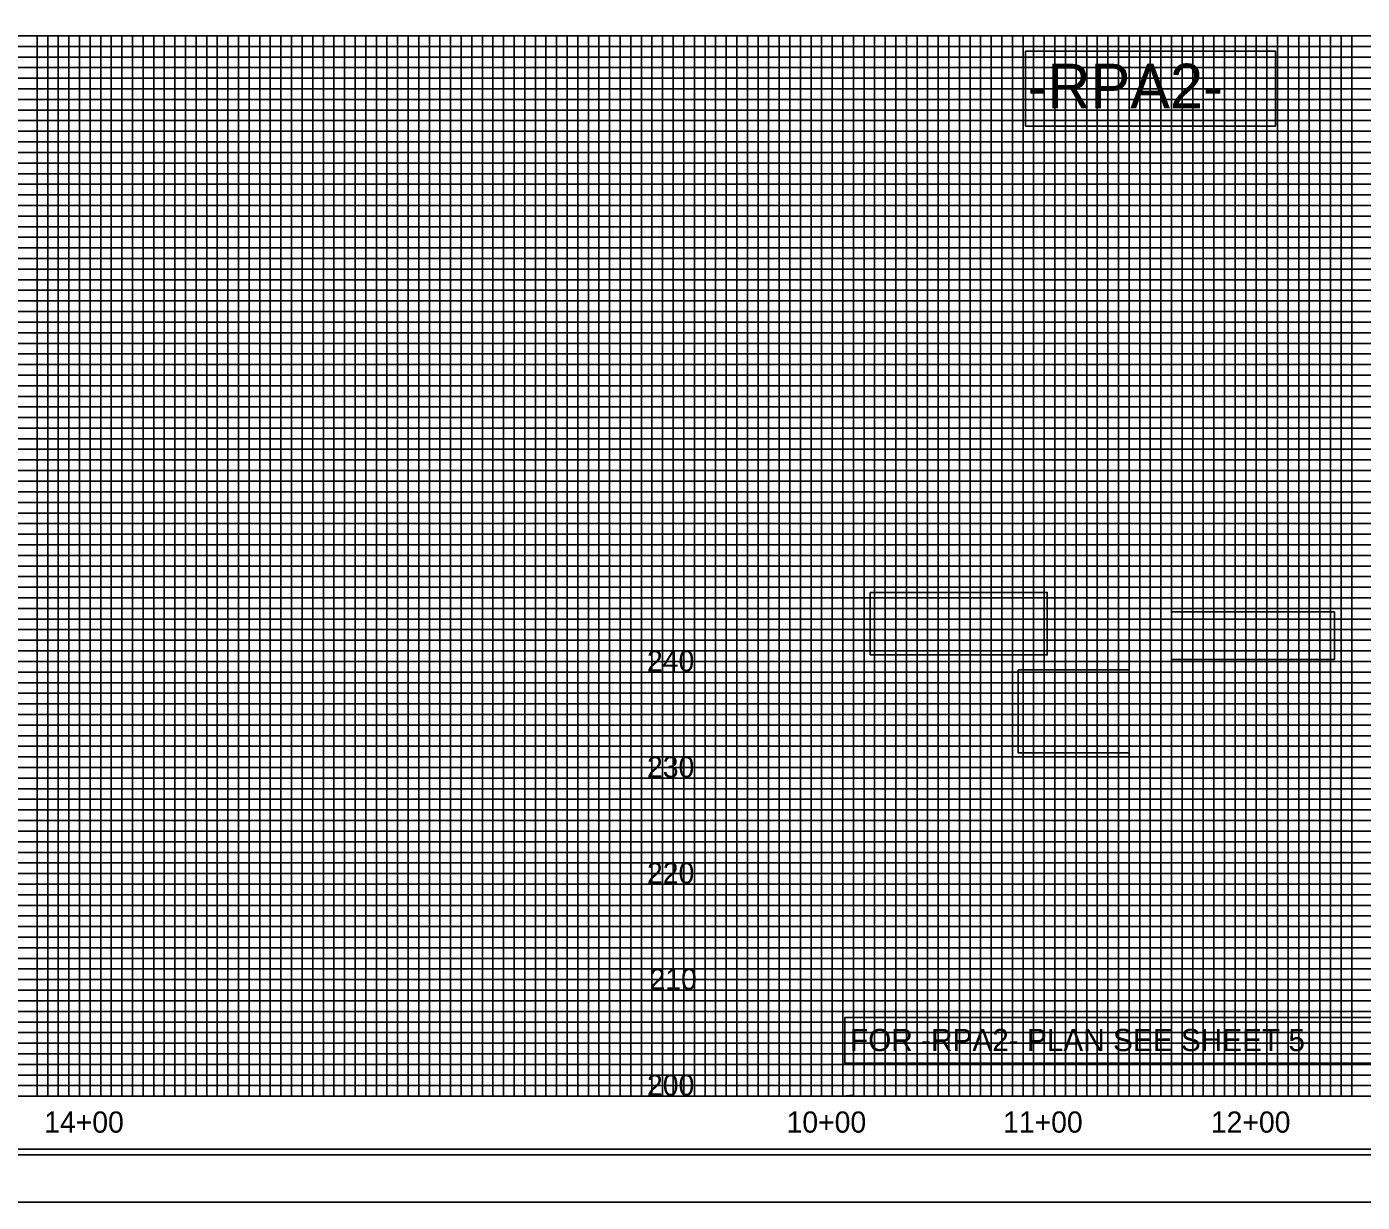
# Model space of a CAD drawing. Extents: x 1810963 to 1812908, y 722070 to 723170.
# Drawn here: x 1811601 to 1812230, y 722070 to 722624 of the extents above; entities that cross this region are included whole.
import ezdxf

# ---------------------------------------------------------------- set-up
doc = ezdxf.new("R2010")
doc.units = 0
for name, color, linetype in [('Exist Horizontal Alignment Tick Label', 7, 'Continuous'), ('Old_Level_11', 7, 'Continuous'), ('Old_Level_2', 7, 'Continuous'), ('Prop Conc 2ft 6in Curb and Gutter', 7, 'Continuous'), ('Prop PFL VPI Symbol CELL', 7, 'Continuous'), ('Prop RDY Traffic Signal CELL', 7, 'Continuous'), ('Prop Shade Heavy', 7, 'Continuous'), ('Prop Shade Light', 7, 'Continuous'), ('Sheet Block Title CELL', 7, 'Continuous'), ('Sheet North Arrow CELL', 7, 'Continuous'), ('Sheet Symbology CELL', 7, 'Continuous'), ('Sheet Title CELL', 7, 'Continuous')]:
    doc.layers.add(name, color=color, linetype=linetype)

msp = doc.modelspace()

# ---------------------------------------------------------------- linework, layer by layer
at = {"layer": 'Old_Level_11'}
msp.add_lwpolyline([(1810976.46, 722092.33), (1812642.96, 722092.33), (1812642.96, 723147.43), (1810976.46, 723147.43)], close=True, dxfattribs=at)
at = {"layer": 'Old_Level_2'}
for p, q in [((1811930.46, 722594.88), (1811880.46, 722594.88)), ((1811930.46, 722569.88), (1811880.46, 722569.88)), ((1811930.46, 722544.88), (1811880.46, 722544.88)), ((1811930.46, 722519.88), (1811880.46, 722519.88)), ((1811930.46, 722494.88), (1811880.46, 722494.88)), ((1811930.46, 722469.88), (1811880.46, 722469.88)), ((1811930.46, 722444.88), (1811880.46, 722444.88)), ((1811930.46, 722419.88), (1811880.46, 722419.88)), ((1811930.46, 722394.88), (1811880.46, 722394.88)), ((1811930.46, 722369.88), (1811880.46, 722369.88)), ((1811930.46, 722344.88), (1811880.46, 722344.88)), ((1811930.46, 722319.88), (1811880.46, 722319.88)), ((1811930.46, 722294.88), (1811880.46, 722294.88)), ((1811930.46, 722269.88), (1811880.46, 722269.88)), ((1811930.46, 722244.88), (1811880.46, 722244.88)), ((1811930.46, 722219.88), (1811880.46, 722219.88)), ((1811930.46, 722194.88), (1811880.46, 722194.88)), ((1811930.46, 722169.88), (1811880.46, 722169.88)), ((1811930.46, 722144.88), (1811880.46, 722144.88))]:
    msp.add_line(p, q, dxfattribs=at)
for points in [[(1811880.46, 722619.88), (1811930.46, 722619.88), (1811930.46, 722119.88), (1811880.46, 722119.88)], [(1812071.6, 722612.66), (1812189.44, 722612.66), (1812189.44, 722577.28), (1812071.6, 722577.28)], [(1811998.41, 722357.41), (1812081.89, 722357.41), (1812081.89, 722327.95), (1811998.41, 722327.95)], [(1812140.53, 722348.22), (1812217.29, 722348.22), (1812217.29, 722325.86), (1812140.53, 722325.86)], [(1812068.08, 722320.86), (1812120.44, 722320.86), (1812120.44, 722281.81), (1812068.08, 722281.81)], [(1811986.45, 722156.96), (1812256.15, 722156.96), (1812256.15, 722135.44), (1811986.45, 722135.44)]]:
    msp.add_lwpolyline(points, close=True, dxfattribs=at)
at = {"layer": 'Prop Conc 2ft 6in Curb and Gutter'}
for p, q in [((1811130.46, 722619.88), (1812630.35, 722619.88)), ((1811630.46, 722619.88), (1811630.46, 722119.88)), ((1811680.46, 722619.88), (1811680.46, 722119.88)), ((1811730.46, 722619.88), (1811730.46, 722119.88)), ((1811780.46, 722619.88), (1811780.46, 722119.88)), ((1811830.46, 722619.88), (1811830.46, 722119.88)), ((1811880.46, 722619.88), (1811880.46, 722119.88)), ((1811880.46, 722619.88), (1811880.46, 722119.88)), ((1811930.46, 722619.88), (1811930.46, 722119.88)), ((1811930.46, 722619.88), (1811930.46, 722119.88)), ((1811980.46, 722619.88), (1811980.46, 722119.88)), ((1812030.46, 722619.88), (1812030.46, 722119.88)), ((1812080.46, 722619.88), (1812080.46, 722119.88)), ((1812130.46, 722619.88), (1812130.46, 722119.88)), ((1812180.46, 722619.88), (1812180.46, 722119.88)), ((1811130.46, 722569.88), (1812630.35, 722569.88)), ((1811130.46, 722519.88), (1812630.35, 722519.88)), ((1811130.46, 722469.88), (1812630.35, 722469.88)), ((1811130.46, 722419.88), (1812630.35, 722419.88)), ((1811130.46, 722369.88), (1812630.35, 722369.88)), ((1811130.46, 722319.88), (1812630.35, 722319.88)), ((1811130.46, 722269.88), (1812630.35, 722269.88)), ((1811130.46, 722219.88), (1812630.35, 722219.88)), ((1811130.46, 722169.88), (1812630.35, 722169.88))]:
    msp.add_line(p, q, dxfattribs=at)
at = {"layer": 'Prop PFL VPI Symbol CELL'}
msp.add_lwpolyline([(1811180.46, 722619.88), (1812580.46, 722619.88), (1812580.46, 722119.88), (1811180.46, 722119.88)], close=True, dxfattribs=at)
at = {"layer": 'Prop RDY Traffic Signal CELL'}
msp.add_line((1810963.46, 722069.88), (1812647.46, 722069.88), dxfattribs=at)
at = {"layer": 'Prop Shade Heavy'}
for p, q in [((1811630.46, 722619.88), (1811680.46, 722619.88)), ((1811730.46, 722619.88), (1811780.46, 722619.88)), ((1811830.46, 722619.88), (1811880.46, 722619.88)), ((1811880.46, 722619.88), (1811930.46, 722619.88)), ((1811930.46, 722619.88), (1811980.46, 722619.88)), ((1812030.46, 722619.88), (1812080.46, 722619.88)), ((1812139.61, 722619.88), (1812189.61, 722619.88))]:
    msp.add_line(p, q, dxfattribs=at)
for points in [[(1811580.46, 722119.88), (1811630.46, 722119.88), (1811630.46, 722619.88), (1811680.46, 722619.88), (1811680.46, 722119.88), (1811730.46, 722119.88), (1811730.46, 722619.88), (1811780.46, 722619.88), (1811780.46, 722119.88), (1811830.46, 722119.88), (1811830.46, 722619.88), (1811880.46, 722619.88), (1811880.46, 722119.88), (1811930.46, 722119.88), (1811930.46, 722619.88), (1811980.46, 722619.88), (1811980.46, 722119.88), (1812030.46, 722119.88), (1812030.46, 722619.88), (1812080.46, 722619.88), (1812080.46, 722119.88), (1812130.46, 722119.88), (1812130.46, 722619.88), (1812180.46, 722619.88), (1812180.46, 722119.88), (1812230.46, 722119.88)], [(1812630.46, 722569.88), (1811130.46, 722569.88)], [(1812630.46, 722519.88), (1811130.46, 722519.88), (1811130.46, 722469.88), (1812630.46, 722469.88)], [(1812630.46, 722419.88), (1811130.46, 722419.88), (1811130.46, 722369.88), (1812630.46, 722369.88)], [(1812630.46, 722319.88), (1811130.46, 722319.88), (1811130.46, 722269.88), (1812630.46, 722269.88)], [(1812630.46, 722219.88), (1811130.46, 722219.88), (1811130.46, 722219.88), (1811130.46, 722169.88), (1812630.46, 722169.88)], [(1812630.46, 722119.88), (1811130.46, 722119.88)]]:
    msp.add_lwpolyline(points, dxfattribs=at)
at = {"layer": 'Prop Shade Light'}
for points in [[(1811555.46, 722619.88), (1811605.46, 722619.88), (1811605.46, 722119.88), (1811655.46, 722119.88), (1811655.46, 722619.88), (1811705.46, 722619.88), (1811705.46, 722119.88), (1811755.46, 722119.88), (1811755.46, 722119.88), (1811755.46, 722619.88), (1811805.46, 722619.88), (1811805.46, 722119.88), (1811855.46, 722119.88), (1811855.46, 722619.88), (1811905.46, 722619.88), (1811905.46, 722119.88), (1811955.46, 722119.88), (1811955.46, 722619.88), (1812005.46, 722619.88), (1812005.46, 722119.88), (1812055.46, 722119.88), (1812055.46, 722619.88), (1812105.46, 722619.88), (1812105.46, 722119.88), (1812155.46, 722119.88), (1812155.46, 722619.88), (1812205.46, 722619.88), (1812205.46, 722119.88), (1812255.46, 722119.88)], [(1811130.46, 722594.88), (1812630.46, 722594.88)], [(1812630.46, 722544.88), (1811130.46, 722544.88), (1811130.46, 722494.88), (1812630.46, 722494.88)], [(1812630.46, 722444.88), (1811130.46, 722444.88), (1811130.46, 722394.88), (1812630.46, 722394.88)], [(1812630.46, 722344.88), (1811130.46, 722344.88), (1811130.46, 722294.88), (1812630.46, 722294.88)], [(1812630.46, 722244.88), (1811130.46, 722244.88), (1811130.46, 722194.88), (1812630.46, 722194.88)], [(1812630.46, 722144.88), (1811130.46, 722144.88)]]:
    msp.add_lwpolyline(points, dxfattribs=at)
at = {"layer": 'Sheet North Arrow CELL'}
msp.add_lwpolyline([(1810963.46, 722069.88), (1812647.46, 722069.88), (1812647.46, 723169.88), (1810963.46, 723169.88)], close=True, dxfattribs=at)
at = {"layer": 'Sheet Symbology CELL'}
for p, q in [((1811130.46, 722619.88), (1812630.46, 722619.88)), ((1812630.46, 722119.88), (1811130.46, 722119.88)), ((1811130.46, 722094.88), (1812630.46, 722094.88))]:
    msp.add_line(p, q, dxfattribs=at)
msp.add_lwpolyline([(1812630.46, 723144.88), (1811130.46, 723144.88), (1811130.46, 722094.88), (1812630.46, 722094.88)], close=True, dxfattribs=at)
at = {"layer": 'Sheet Title CELL'}
for p, q in [((1811180.46, 722614.88), (1812580.46, 722614.88)), ((1812580.46, 722609.88), (1811180.46, 722609.88)), ((1811180.46, 722604.88), (1812580.46, 722604.88)), ((1812580.46, 722599.88), (1811180.46, 722599.88)), ((1811180.46, 722589.88), (1812580.46, 722589.88)), ((1812580.46, 722584.88), (1811180.46, 722584.88)), ((1811180.46, 722579.88), (1812580.46, 722579.88)), ((1812580.46, 722574.88), (1811180.46, 722574.88)), ((1811180.46, 722564.88), (1812580.46, 722564.88)), ((1812580.46, 722559.88), (1811180.46, 722559.88)), ((1811180.46, 722554.88), (1812580.46, 722554.88)), ((1812580.46, 722549.88), (1811180.46, 722549.88)), ((1811180.46, 722539.88), (1812580.46, 722539.88)), ((1812580.46, 722534.88), (1811180.46, 722534.88)), ((1811180.46, 722529.88), (1812580.46, 722529.88)), ((1812580.46, 722524.88), (1811180.46, 722524.88)), ((1811180.46, 722514.88), (1812580.46, 722514.88)), ((1812580.46, 722509.88), (1811180.46, 722509.88)), ((1811180.46, 722504.88), (1812580.46, 722504.88)), ((1812580.46, 722499.88), (1811180.46, 722499.88)), ((1811180.46, 722489.88), (1812580.46, 722489.88)), ((1812580.46, 722484.88), (1811180.46, 722484.88)), ((1811180.46, 722479.88), (1812580.46, 722479.88)), ((1812580.46, 722474.88), (1811180.46, 722474.88)), ((1811180.46, 722464.88), (1812580.46, 722464.88)), ((1812580.46, 722459.88), (1811180.46, 722459.88)), ((1811180.46, 722454.88), (1812580.46, 722454.88)), ((1812580.46, 722449.88), (1811180.46, 722449.88)), ((1811180.46, 722439.88), (1812580.46, 722439.88)), ((1812580.46, 722434.88), (1811180.46, 722434.88)), ((1811180.46, 722429.88), (1812580.46, 722429.88)), ((1812580.46, 722424.88), (1811180.46, 722425.03)), ((1811180.46, 722414.88), (1812580.46, 722414.88)), ((1812580.46, 722409.88), (1811180.46, 722409.88)), ((1811180.46, 722404.88), (1812580.46, 722404.88)), ((1812580.46, 722399.88), (1811180.46, 722399.88)), ((1811180.46, 722389.88), (1812580.46, 722389.88)), ((1812580.46, 722384.88), (1811180.46, 722384.88)), ((1811180.46, 722379.88), (1812580.46, 722379.88)), ((1812580.46, 722374.88), (1811180.46, 722374.88)), ((1811180.46, 722364.88), (1812580.46, 722364.88)), ((1812580.46, 722359.88), (1811180.46, 722359.88)), ((1811180.46, 722354.88), (1812580.46, 722354.88)), ((1812580.46, 722349.88), (1811180.46, 722349.88)), ((1811180.46, 722339.88), (1812580.46, 722339.88)), ((1812580.46, 722334.88), (1811180.46, 722334.88)), ((1811180.46, 722329.88), (1812580.46, 722329.88)), ((1812580.46, 722324.88), (1811180.46, 722324.88)), ((1811180.46, 722314.88), (1812580.46, 722314.88)), ((1812580.46, 722309.88), (1811180.46, 722309.88)), ((1811180.46, 722304.88), (1812580.46, 722304.88)), ((1812580.46, 722299.88), (1811180.46, 722299.88)), ((1811180.46, 722289.88), (1812580.46, 722289.88)), ((1812580.46, 722284.88), (1811180.46, 722284.88)), ((1811180.46, 722279.88), (1812580.46, 722279.88)), ((1812580.46, 722274.88), (1811180.46, 722274.88)), ((1811180.46, 722264.88), (1812580.46, 722264.88)), ((1812580.46, 722259.88), (1811180.46, 722259.88)), ((1811180.46, 722254.88), (1812580.46, 722254.88)), ((1812580.46, 722249.88), (1811180.46, 722249.88)), ((1811180.46, 722239.88), (1812580.46, 722239.88)), ((1812580.46, 722234.88), (1811180.46, 722234.88)), ((1811180.46, 722229.88), (1812580.46, 722229.88)), ((1812580.46, 722224.88), (1811180.46, 722224.88)), ((1811180.46, 722214.88), (1812580.46, 722214.88)), ((1812580.46, 722209.88), (1811180.46, 722209.88)), ((1811180.46, 722204.88), (1812580.46, 722204.88)), ((1812580.46, 722199.88), (1811180.46, 722199.88)), ((1811180.46, 722189.88), (1812580.46, 722189.88)), ((1812580.46, 722184.88), (1811180.46, 722184.88)), ((1811180.46, 722179.88), (1812580.46, 722179.88)), ((1812580.46, 722174.88), (1811180.46, 722174.88)), ((1811180.46, 722164.88), (1812580.46, 722164.88)), ((1812580.46, 722159.88), (1811180.46, 722159.88)), ((1811180.46, 722154.88), (1812580.46, 722154.88)), ((1812580.46, 722149.88), (1811180.46, 722149.88)), ((1811180.46, 722139.88), (1812580.46, 722139.88)), ((1812580.46, 722134.88), (1811180.46, 722134.88)), ((1811180.46, 722129.88), (1812580.46, 722129.88)), ((1811180.46, 722124.88), (1812580.46, 722124.88))]:
    msp.add_line(p, q, dxfattribs=at)
for points in [[(1811600.46, 722619.88), (1811610.46, 722619.88), (1811610.46, 722119.88), (1811615.46, 722119.88), (1811615.46, 722619.88), (1811620.46, 722619.88), (1811620.46, 722119.88), (1811625.46, 722119.88), (1811625.46, 722619.88), (1811635.46, 722619.88), (1811635.46, 722119.88), (1811640.46, 722119.88), (1811640.46, 722619.88), (1811645.46, 722619.88), (1811645.46, 722119.88), (1811650.46, 722119.88), (1811650.46, 722619.88), (1811660.46, 722619.88), (1811660.46, 722119.88), (1811665.46, 722119.88), (1811665.46, 722619.88), (1811670.46, 722619.88), (1811670.46, 722119.88), (1811675.46, 722119.88), (1811675.46, 722619.88), (1811685.46, 722619.88), (1811685.46, 722119.88), (1811690.46, 722119.88), (1811690.46, 722619.88), (1811695.46, 722619.88), (1811695.46, 722119.88), (1811700.46, 722119.88), (1811700.46, 722619.88), (1811710.46, 722619.88)], [(1811710.46, 722619.88), (1811710.46, 722119.88), (1811715.46, 722119.88), (1811715.46, 722619.88), (1811720.46, 722619.88), (1811720.46, 722119.88), (1811725.46, 722119.88), (1811725.46, 722619.88), (1811735.46, 722619.88), (1811735.46, 722119.88), (1811740.46, 722119.88), (1811740.46, 722619.88), (1811745.46, 722619.88), (1811745.46, 722119.88), (1811750.46, 722119.88), (1811750.46, 722619.88), (1811760.46, 722619.88), (1811760.46, 722119.88), (1811765.46, 722119.88), (1811765.46, 722619.88), (1811770.46, 722619.88), (1811770.46, 722119.88), (1811775.46, 722119.88), (1811775.46, 722619.88), (1811785.46, 722619.88), (1811785.46, 722119.88), (1811790.46, 722119.88), (1811790.46, 722619.88), (1811795.46, 722619.88), (1811795.46, 722119.88), (1811800.46, 722119.88), (1811800.46, 722619.88), (1811810.46, 722619.88), (1811810.46, 722119.88), (1811815.46, 722119.88), (1811815.46, 722619.88), (1811820.46, 722619.88), (1811820.46, 722119.88), (1811825.46, 722119.88), (1811825.46, 722619.88), (1811835.46, 722619.88), (1811835.46, 722119.88), (1811835.46, 722119.88), (1811840.46, 722119.88), (1811840.46, 722619.88), (1811845.46, 722619.88), (1811845.46, 722119.88), (1811850.46, 722119.88), (1811850.46, 722619.88), (1811860.46, 722619.88), (1811860.46, 722119.88), (1811865.46, 722119.88), (1811865.46, 722619.88), (1811870.46, 722619.88), (1811870.46, 722119.88), (1811875.46, 722119.88), (1811875.46, 722619.88), (1811885.46, 722619.88), (1811885.46, 722119.88), (1811890.46, 722119.88), (1811890.46, 722619.88), (1811895.46, 722619.88), (1811895.46, 722119.88), (1811900.46, 722119.88), (1811900.46, 722619.88), (1811910.46, 722619.88), (1811910.46, 722119.88), (1811915.46, 722119.88), (1811915.46, 722619.88), (1811920.46, 722619.88), (1811920.46, 722119.88), (1811925.46, 722119.88), (1811925.46, 722619.88), (1811935.46, 722619.88), (1811935.46, 722119.88), (1811940.46, 722119.88), (1811940.46, 722619.88), (1811945.46, 722619.88), (1811945.46, 722119.88), (1811950.46, 722119.88), (1811950.46, 722619.88), (1811960.46, 722619.88), (1811960.46, 722119.88), (1811965.46, 722119.88), (1811965.46, 722619.88), (1811970.46, 722619.88), (1811970.46, 722119.88), (1811975.46, 722119.88), (1811975.46, 722619.88), (1811985.46, 722619.88), (1811985.46, 722119.88), (1811990.16, 722120.43), (1811990.46, 722119.88), (1811990.46, 722619.88), (1811995.46, 722619.88), (1811995.46, 722119.88), (1812000.46, 722119.88), (1812000.46, 722619.88), (1812010.46, 722619.88), (1812010.46, 722119.88), (1812015.46, 722119.88)], [(1812015.46, 722119.88), (1812015.46, 722619.88), (1812020.46, 722619.88), (1812020.46, 722119.88), (1812025.46, 722119.88), (1812025.46, 722619.88), (1812035.46, 722619.88), (1812035.46, 722119.88), (1812040.46, 722119.88), (1812040.46, 722619.88), (1812045.46, 722619.88), (1812045.46, 722119.88), (1812050.46, 722119.88), (1812050.46, 722619.88), (1812060.46, 722619.88), (1812060.46, 722119.88), (1812065.46, 722119.88), (1812065.46, 722619.88), (1812070.46, 722619.88), (1812070.46, 722119.88), (1812075.46, 722119.88), (1812075.46, 722619.88), (1812085.46, 722619.88), (1812085.46, 722119.88), (1812090.46, 722119.88), (1812090.46, 722619.88), (1812095.46, 722619.88), (1812095.46, 722119.88), (1812100.46, 722119.88), (1812100.46, 722619.88), (1812110.46, 722619.88), (1812110.46, 722119.88), (1812115.46, 722119.88), (1812115.46, 722619.88), (1812120.46, 722619.88), (1812120.46, 722119.88), (1812125.46, 722119.88), (1812125.46, 722619.88), (1812135.46, 722619.88), (1812135.46, 722119.88), (1812140.46, 722119.88), (1812140.46, 722619.88), (1812145.46, 722619.88), (1812145.46, 722119.88), (1812150.46, 722119.88), (1812150.46, 722619.88), (1812160.46, 722619.88), (1812160.46, 722119.88), (1812165.46, 722119.88), (1812165.46, 722619.88), (1812170.46, 722619.88), (1812170.46, 722119.88), (1812175.46, 722119.88), (1812175.46, 722619.88), (1812185.46, 722619.88), (1812185.46, 722119.88), (1812190.46, 722119.88), (1812190.46, 722619.88), (1812195.46, 722619.88), (1812195.46, 722119.88), (1812200.46, 722119.88), (1812200.46, 722619.88), (1812210.46, 722619.88), (1812210.46, 722119.88), (1812215.46, 722119.88), (1812215.46, 722619.88), (1812220.46, 722619.88), (1812220.46, 722119.88), (1812225.46, 722119.88), (1812225.46, 722619.88), (1812235.46, 722619.88)]]:
    msp.add_lwpolyline(points, dxfattribs=at)

# ---------------------------------------------------------------- texts
at = {"layer": 'Exist Horizontal Alignment Tick Label'}
for s, height, p in [('-RPA2-', 21, (1812072.67, 722585.71)), ('FOR -RPA2- PLAN SEE SHEET 5', 10.5, (1811988.84, 722141.15))]:
    msp.add_text(s, height=height, rotation=360, dxfattribs=at).set_placement(p)
at = {"layer": 'Old_Level_2'}
for s, p in [('240', (1811893.1, 722320.13)), ('230', (1811893.1, 722270.13)), ('220', (1811893.1, 722220.13)), ('210', (1811894.29, 722170.13)), ('200', (1811893.1, 722120.13))]:
    msp.add_text(s, height=10, dxfattribs=at).set_placement(p)
at = {"layer": 'Sheet Block Title CELL'}
for s, p in [('14+00', (1811608.81, 722102.7)), ('10+00', (1811958.92, 722102.7)), ('11+00', (1812061.03, 722102.7)), ('12+00', (1812159.01, 722102.7))]:
    msp.add_text(s, height=10, dxfattribs=at).set_placement(p)

doc.saveas('drawing.dxf')
